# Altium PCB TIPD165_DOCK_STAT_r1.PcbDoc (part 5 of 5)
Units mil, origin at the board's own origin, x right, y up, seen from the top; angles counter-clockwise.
Board outline 6950 x 2800 mil, 2 copper layers (Primary Side, Secondary Side), stack 12.7 mil thick; 32 components, 163 nets, 1211 pads, 80 vias.
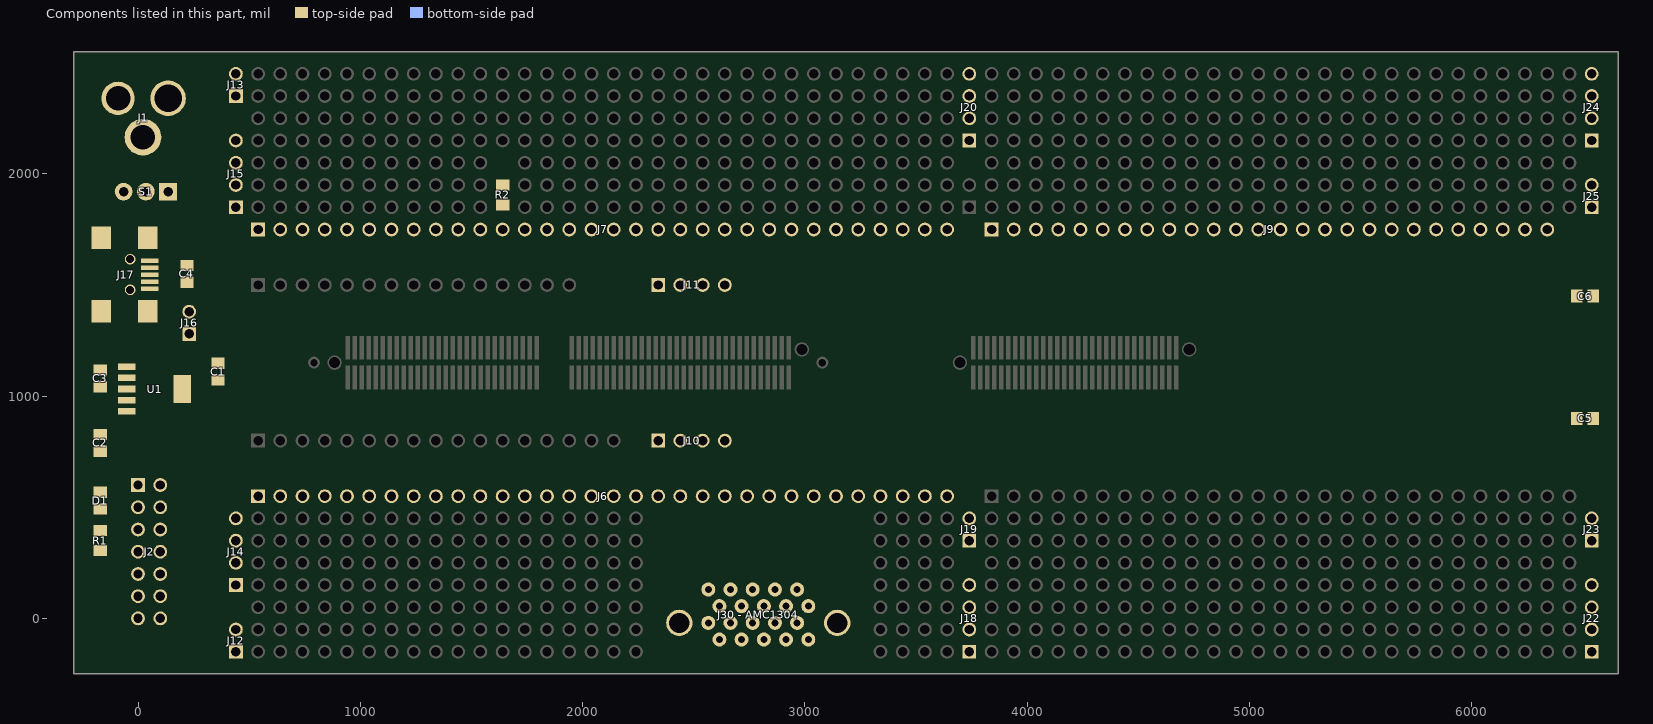
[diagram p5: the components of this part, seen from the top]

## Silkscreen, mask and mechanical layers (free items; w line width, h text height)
Primary Silkscreen:
  circle w8: c5627.38,1435 r12.38
  lines w8: 5604.5,1346.5 5609.75,1346.5 5624,1411.75 5619.5,1411.75 ; 5604.68,1346.37 5618.93,1411.62 ; 5491.25,1381 5493.5,1375.75 5497.25,1369.75 5510,1359.25 5516.75,1350.25 5525,1337.5 5535.5,1331.5 5543.75,1331.5 5547.5,1334.5 5555,1339.75 5558,1338.25 5562.5,1333.75 5568.5,1325.5 5576.75,1312.75 5576.75,1309 5580.5,1299.25 5584.25,1294 5591,1285.75 5603.75,1279.75 5613.5,1274.5 5621,1273.75 5623.25,1276 5624.75,1279.75 5623.25,1282.75 5621.75,1287.25 5621,1294 5624,1303.75 5627,1309.75 5634.5,1314.25 5640.5,1317.25 5648.75,1321 5656.25,1324 5665.25,1327 5675.75,1331.5 5684.75,1335.25 5687,1338.25 5689.25,1346.5 5689.25,1351.75 5687.75,1359.25 5687.75,1364.5 5684.75,1370.5 5681.75,1375.75 5678.75,1378 5677.25,1381 5677.25,1387.75 5676.5,1394.5 5675.75,1400.5 5674.25,1403.5 5675.75,1403.5 5674.25,1407.25 5671.25,1411 5668.25,1411.75 5663,1412.5 5660.75,1412.5 5660,1414 5651.75,1414 5648,1412.5 5645,1412.5 5639.75,1412.5 5638.25,1411.75 5634.5,1411 5629.25,1389.25 5649.5,1389.25 5646.5,1376.5 5627,1376.5 5620.25,1345.75 5621.75,1345 5623.25,1343.5 5624,1342 5624,1340.5 5624,1337.5 5621.75,1335.25 5621.75,1334.5 5615.75,1332.25 5612,1331.5 5607.5,1331.5 5601.5,1333.75 5596.25,1336.75 5593.25,1339.75 5593.25,1342 5601.5,1376.5 5580.5,1376.5 5585,1390 5603.75,1390 5609.75,1412.5 5606.75,1414 5600,1417 5598.5,1420 5594,1423.75 5594,1458.25 5543,1458.25 5543,1381 5491.25,1381
  lines w10: 899.69,998.13 598.28,998.13 598.28,1303.72 899.69,1303.72 ; 1828.08,998.13 1916.18,998.13 ; 1828.08,1303.72 1916.18,1303.72 ; 2970.56,998.13 3271.98,998.13 3271.98,1258.72 3226.98,1303.72 2970.56,1303.72 ; 3713.39,998.13 3635.4,998.13 3635.4,1303.72 3713.39,1303.72 ; 4712,998.13 4791.39,998.13 4791.39,1273.72 4761.39,1303.72 4713,1303.72 ; 490,750 490,850 2190,850 2190,750 490,750 ; 490,1450 490,1550 1990,1550 1990,1450 490,1450 ; 3690,1800 3790,1800 3790,2000 3690,2000 3690,1800 ; 3790,500 3790,600 6490,600 6490,500 3790,500
  text "GND" at 371.5,2355.69 h35 r90
  text "+5V in" at 293.33,2128.7 h35 r90
  text "GND" at 3755.75,2022.82 h27.5 r90
  text "GND" at 6555.75,2022.82 h27.5 r90
  text "3V3" at 371.5,1864.35 h35 r90
  text "EXT-ON" at -153.5,1845.37 h35 r90
  text "USB-ON" at 262.5,1836.21 h35 r90
  text "3V3" at 3755.75,1726.21 h27.5 r90
  text "3V3" at 6555.75,1725.71 h27.5 r90
  text "PIN" at 465,1700 h40 r90
  text "56" at 865,1632.63 h40 r90
  text "60" at 1065,1632.82 h40 r90
  text "62" at 1165,1632.82 h40 r90
  text "68" at 1365,1632.82 h40 r90
  text "76" at 1765,1632.63 h40 r90
  text "86" at 2165,1632.63 h40 r90
  text "96" at 2665,1632.63 h40 r90
  text "50" at 565,1630.73 h40 r90
  text "52" at 665,1630.73 h40 r90
  text "58" at 965,1630.73 h40 r90
  text "64" at 1265,1630.92 h40 r90
  text "70" at 1465,1630.73 h40 r90
  text "72" at 1565,1630.73 h40 r90
  text "78" at 1865,1630.73 h40 r90
  text "80" at 1965,1630.73 h40 r90
  text "82" at 2065,1630.73 h40 r90
  text "88" at 2265,1630.73 h40 r90
  text "90" at 2365,1630.73 h40 r90
  text "92" at 2465,1630.73 h40 r90
  text "54" at 765,1628.82 h40 r90
  text "74" at 1665,1628.82 h40 r90
  text "94" at 2565,1628.82 h40 r90
  text "116" at 3465,1609.59 h40 r90
  text "110" at 3265,1607.68 h40 r90
  text "118" at 3565,1607.68 h40 r90
  text "114" at 3365,1605.78 h40 r90
  text "166" at 5865,1605.4 h40 r90
  text "106" at 3065,1603.3 h40 r90
  text "126" at 4065,1603.3 h40 r90
  text "146" at 4965,1603.3 h40 r90
  text "156" at 5465,1603.3 h40 r90
  text "160" at 5565,1603.5 h40 r90
  text "162" at 5665,1603.5 h40 r90
  text "168" at 5965,1603.5 h40 r90
  text "176" at 6365,1603.3 h40 r90
  text "164" at 5765,1601.59 h40 r90
  text "100" at 2765,1601.4 h40 r90
  text "102" at 2865,1601.4 h40 r90
  text "108" at 3165,1601.4 h40 r90
  text "120" at 3665,1601.4 h40 r90
  text "122" at 3865,1601.4 h40 r90
  text "128" at 4165,1601.4 h40 r90
  text "130" at 4265,1601.4 h40 r90
  text "132" at 4365,1601.4 h40 r90
  text "138" at 4565,1601.4 h40 r90
  text "140" at 4665,1601.4 h40 r90
  text "142" at 4765,1601.4 h40 r90
  text "148" at 5065,1601.4 h40 r90
  text "150" at 5165,1601.4 h40 r90
  text "152" at 5265,1601.4 h40 r90
  text "170" at 6065,1601.4 h40 r90
  text "172" at 6165,1601.4 h40 r90
  text "104" at 2965,1599.5 h40 r90
  text "124" at 3965,1599.5 h40 r90
  text "134" at 4465,1599.5 h40 r90
  text "144" at 4865,1599.5 h40 r90
  text "154" at 5365,1599.5 h40 r90
  text "174" at 6265,1599.5 h40 r90
  text "ANA" at 465,1445 h40 r90
  text "16" at 765,1385.92 h40 r90
  text "12" at 565,1384.01 h40 r90
  text "18" at 865,1384.01 h40 r90
  text "14" at 665,1382.11 h40 r90
  text "26" at 1165,1379.63 h40 r90
  text "36" at 1665,1379.63 h40 r90
  text "20" at 965,1377.73 h40 r90
  text "28" at 1265,1377.73 h40 r90
  text "30" at 1365,1377.73 h40 r90
  text "32" at 1465,1377.73 h40 r90
  text "40" at 1765,1377.73 h40 r90
  text "42" at 1865,1377.73 h40 r90
  text "24" at 1065,1375.82 h40 r90
  text "44" at 1965,1375.82 h40 r90
  text "GND" at 2440,1375 h40
  text "34" at 1565,1370.82 h40 r90
  text "5V" at 352.5,1302.18 h35 r90
  text "POWER ONLY" at -180.77,1267.5 h35
  text "TEXAS INSTRUMENTS" at 5238.44,1156.51 h75
  text "TIPD165 Docking Station [Rev. 1]" at 5221.92,1015.48 h50
  text "GND" at 2440,875 h40
  text "11" at 665,870 h40 r90
  text "13" at 765,870 h40 r90
  text "15" at 865,870 h40 r90
  text "17" at 965,870 h40 r90
  text "09" at 565,865 h40 r90
  text "21" at 1065,865 h40 r90
  text "23" at 1165,865 h40 r90
  text "25" at 1265,865 h40 r90
  text "27" at 1365,865 h40 r90
  text "29" at 1465,865 h40 r90
  text "31" at 1565,865 h40 r90
  text "33" at 1665,865 h40 r90
  text "37" at 1765,865 h40 r90
  text "39" at 1865,865 h40 r90
  text "41" at 1965,865 h40 r90
  text "43" at 2065,865 h40 r90
  text "45" at 2165,865 h40 r90
  text "ANA" at 465,745 h40 r90
  text "49" at 565,615 h40 r90
  text "51" at 665,615 h40 r90
  text "53" at 765,615 h40 r90
  text "55" at 865,615 h40 r90
  text "57" at 965,615 h40 r90
  text "59" at 1065,615 h40 r90
  text "61" at 1165,615 h40 r90
  text "63" at 1265,615 h40 r90
  text "67" at 1365,615 h40 r90
  text "69" at 1465,615 h40 r90
  text "71" at 1565,615 h40 r90
  text "73" at 1665,615 h40 r90
  text "75" at 1765,615 h40 r90
  text "77" at 1865,615 h40 r90
  text "79" at 1965,615 h40 r90
  text "81" at 2065,615 h40 r90
  text "85" at 2165,615 h40 r90
  text "87" at 2265,615 h40 r90
  text "89" at 2365,615 h40 r90
  text "91" at 2465,615 h40 r90
  text "93" at 2565,615 h40 r90
  text "95" at 2665,615 h40 r90
  text "99" at 2765,615 h40 r90
  text "101" at 2865,615 h40 r90
  text "103" at 2965,615 h40 r90
  text "105" at 3065,615 h40 r90
  text "107" at 3165,615 h40 r90
  text "109" at 3265,615 h40 r90
  text "113" at 3365,615 h40 r90
  text "115" at 3465,615 h40 r90
  text "117" at 3565,615 h40 r90
  text "119" at 3665,615 h40 r90
  text "121" at 3865,615 h40 r90
  text "123" at 3965,615 h40 r90
  text "125" at 4065,615 h40 r90
  text "127" at 4165,615 h40 r90
  text "129" at 4265,615 h40 r90
  text "131" at 4365,615 h40 r90
  text "133" at 4465,615 h40 r90
  text "137" at 4565,615 h40 r90
  text "139" at 4665,615 h40 r90
  text "141" at 4765,615 h40 r90
  text "143" at 4865,615 h40 r90
  text "145" at 4965,615 h40 r90
  text "147" at 5065,615 h40 r90
  text "149" at 5165,615 h40 r90
  text "151" at 5265,615 h40 r90
  text "153" at 5365,615 h40 r90
  text "155" at 5465,615 h40 r90
  text "159" at 5565,615 h40 r90
  text "161" at 5665,615 h40 r90
  text "163" at 5765,615 h40 r90
  text "165" at 5865,615 h40 r90
  text "167" at 5965,615 h40 r90
  text "169" at 6065,615 h40 r90
  text "171" at 6165,615 h40 r90
  text "173" at 6265,615 h40 r90
  text "175" at 6365,615 h40 r90
  text "177" at 6465,615 h40 r90
  text "1" at -76,585 h25
  text "3V3" at 3755.75,525.71 h27.5 r90
  text "3V3" at 6555.75,525.71 h27.5 r90
  text "PIN" at 465,515 h40 r90
  text "GND" at 3755.75,222.82 h27.5 r90
  text "GND" at 6555.75,222.82 h27.5 r90
  text "3V3" at 371.5,150 h35 r90
  text "14" at 166,-16 h25
  text "JTAG" at -45,-150 h50
  text "GND" at 371.5,-150 h35 r90
  text "Primary Side Silkscreen" at 7579.95,-4801.77 h75
Drill Drawing:
  drawing of 181 lines, arcs and shapes, not listed
  text "Layer 1 - Primary Side" at -890,5272.73 h75
  text "Finished - 3 oz. Copper" at -3541,5265 h50
  text "Er = 4.3 - THICKNESS = FABRICATOR MAY DETERMINE" at -4274.62,4968.26 h62.5
  text "0.062\" +/- 0.007\"" at -6474.14,4956.65 h75
  text "Finished  - 3 oz. Copper" at -3561,4655 h50
  text "Layer 2 - Secondary Side" at -890,4647.73 h75
  text "FABRICATION NOTES:" at -6316,4090 h56.25
  text "1. NUMBER OF LAYERS = 2" at -6316,3865 h56.25
  text "2. UNLESS OTHERWISE SPECIFIED THE PRINTED WIRING BOARD" at -6334.75,3733.75 h56.25
  text "SHALL MEET THE REQUIREMENTS OF IPC-6012 CLASS 2." at -6184.75,3583.75 h56.25
  text "3. ACCEPTABILIITY TO IPC-A-600 CLASS 2." at -6336,3420 h56.25
  text "4. MATERIAL:" at -6334.75,3265 h56.25
  text "A. TYPE: FR4 OR EQUIVALENT" at -6091,3115 h56.25
  text "B. RAW Cu WEIGHT OUTER LAYERS:  2 Oz." at -6091,2965 h56.25
  text "C. RAW Cu WEIGHT INNER SIGNAL LAYERS:  N/A" at -6085,2825 h56.25
  text "D. RAW Cu WEIGHT INNER PLANE LAYERS:  N/A" at -6091,2665 h56.25
  text "E.     HI Tg      RoHS       HALOGEN FREE" at -6091,2515 h56.25
  text "2550mils" at -1420,2510 h75
  text "5. PROCESSING:" at -6316,2365 h56.25
  text "A. COPPER THEIVING ALLOWED ON OUTER LAYERS KEEPING A MINIMUM OF 0.200'" at -6091,2215 h56.25
  text "B. REMOVE ALL UNUSED PADS ON ARTWORK ON ALL INNER LAYERS." at -6091,2065 h56.25
  text "C. ETCH DATE CODE AND UL RECOGNIZED VENDOR MARK ON SECONDARY SIDE." at -6091,1915 h56.25
  text "6. IMPEDANCE:" at -6316,1765 h56.25
  text "A. USE REQUIRMENTS IN STACKUP. FABRICATOR HAS PERMISSION TO CHANGE THICKNESS" at -6091,1615 h56.25
  text "AND TRACE WIDTHS IN ORDER TO MEET IMPEDANCE REQUIRMENTS." at -5941,1465 h56.25
  text "55mil" at 1130,1340 h75 r90
  text "0" at 746.25,1319.32 h75 r90
  text "B. NON-CONTROLLED TRACES TO BE WITHIN 20% OF SPECIFIED APERTURE" at -6091,1315 h56.25
  text "0" at 1113.75,1264.04 h75 r90
  text "VALUE IN ARTWORK." at -5941,1165 h56.25
  text "-55mil" at 790,1120 h75 r90
  text "7. Cu PLATING:" at -6316,1015 h56.25
  text "A. UNLESS OTHERWISE SPECIFIED, HOLE DIMENSIONS ARE FOR FINISHED HOLES." at -6091,865 h56.25
  text "B. UNLESS OTHERWISE SPECIFIED, HOLE BARREL THICKNESS TO BE 0.001\" MIN." at -6091,715 h56.25
  text "8. FINISH PLATING:" at -6316,565 h56.25
  text "FINISH ALL EXPOSED PADS WITH:" at -5341,565 h56.25
  text "ELECTROLESS NICKEL/IMMERSION GOLD (ENIG)" at -5716,415 h56.25
  text "IMMERSION SILVER (ENIG)" at -5716,265 h56.25
  text "TIN/LEAD (HASL)" at -5716,115 h56.25
  text "HARD GOLD OVER NICKEL  30u/80u" at -5716,-35 h56.25
  text "0" at -940,-45 h75
  text "WHITE TIN" at -5716,-185 h56.25
  text "-250mils" at -1440,-295 h75
  text "ORGANIC SOLDERABILITY PRESERVATIVE (OSP)" at -5716,-335 h56.25
  text "LEAD FREE HASL" at -5716,-485 h56.25
  text "9. SOLDERMASK:" at -6316,-635 h56.25
  text "A. LPI GREEN SOLDER MASK OVER BARE COPPER BOTH SIDES." at -6091,-785 h56.25
  text "B. SOLDER MASK REGISTRATION TO BE WITHIN +/-.003\" OF RELEVANT LAYER." at -6091,-935 h56.25
  text "0" at 50,-940 h75 r90
  text "C. NO MASK TO APPEAR ON PADS" at -6091,-1085 h56.25
  text "6660mils" at 6700,-1210 h75 r90
  text "10. SILKSCREEN:" at -6316,-1235 h56.25
  text "A. USE WHITE NON-CONDUCTIVE INK." at -6091,-1385 h56.25
  text "-290mils" at -250,-1420 h75 r90
  text "B. NO SILKSCREEN TO APPEAR ON PADS." at -6091,-1535 h56.25
  text "11. WARP AND TWIST NOT TO EXCEED .010 INCH/INCH." at -6316,-1685 h56.25
  text "12. MILLING:" at -6316,-1835 h56.25
  text "A. ALL BOARD DIMENSIONS TO BE HELD TO WITHIN 0.005\"." at -6091,-1985 h56.25
  text "B. IF NO DIMENSIONS PRESENT, USE BOARD OUTLINE IN DD.PHO (THIS DRAWING)" at -6091,-2135 h56.25
  text "TO FEED DIRECTLY INTO MILLING PROCESSOR." at -5941,-2285 h56.25
  text "12. SPECIAL FEATURES:" at -6316,-2435 h56.25
  text "\"VIA IN PAD\"  PLUGGED [NON-CONDUCTIVE] VIAS PLATED OVER FLAT AND FLUSH" at -5716,-2585 h56.25
  text "\"VIA IN PAD\"  PLUGGED VIAS [CONDUCTIVE] PLATED OVER FLAT AND FLUSH" at -5716,-2735 h56.25
  text "BLIND VIAS" at -5716,-2885 h56.25
  text "BURIED VIAS" at -5716,-3035 h56.25
Primary Assembly Drawing:
  lines w1: -4928.1,-1085.94 -4685.47,-1085.94 ; -4928.1,1485.89 -4685.47,1485.89 ; -4928.1,3766.56 -4685.47,3766.56 ; -4831.83,1363.31 -4701.51,1486.01 -4831.83,1606.14 ; -2744.47,-3851.86 -2744.47,-3609.24 ; -2744.47,6581.01 -2744.47,6823.64 ; -803.47,-3851.86 -803.47,-3609.24 ; -803.47,6581.01 -803.47,6823.64 ; 490,-200 3690,-200 3690,500 490,500 490,400 ; 490,1800 3690,1800 ; 490,2400 490,2500 3690,2500 3690,1800 ; 1258.84,-3851.86 1258.84,-3609.24 ; 1258.84,6581.01 1258.84,6823.64 ; 1822.51,-3606.2 1822.51,-1663.26 ; 1823.78,-2784.18 3691.99,-2784.18 ; 1823.78,-2634.73 3691.99,-2634.73 ; 1823.78,-2485.27 3691.99,-2485.27 ; 1823.78,-2335.81 3691.99,-2335.81 ; 1823.78,-2186.36 3691.99,-2186.36 ; 1823.78,-2036.9 3691.99,-2036.9 ; 1823.78,-1850.08 3691.99,-1850.08 ; 1823.78,-1663.26 11314.31,-1663.26 ; 2757.89,-2784.18 2757.89,-1850.08 ; 3196.13,6725.42 3321.12,6580.83 3446.71,6725.42 ; 3321.15,-3851.86 3321.15,-3609.24 ; 3321.15,6581.01 3321.15,6823.64 ; 3691.99,-3606.2 3691.99,-1663.26 ; 3691.99,-2013.77 5597.57,-2013.77 ; 3790,-200 6540,-200 6540,500 3790,500 ; 3790,400 3790,500 ; 3790,2400 3790,2500 6540,2500 6540,1800 3790,1800 ; 5383.47,-3851.86 5383.47,-3609.24 ; 5383.47,6581.01 5383.47,6823.64 ; 5597.57,-3606.2 5597.57,-1663.26 ; 5597.57,-3456.74 7465.78,-3456.74 ; 5597.57,-3307.28 7465.78,-3307.28 ; 5597.57,-3157.83 7465.78,-3157.83 ; 5597.57,-3008.37 7465.78,-3008.37 11314.31,-3008.37 ; 5597.57,-2858.91 7465.78,-2858.91 ; 5597.57,-2709.45 7465.78,-2709.45 ; 5597.57,-2560 7465.78,-2560 ; 5597.57,-2410.54 7465.78,-2410.54 ; 5597.57,-2261.08 7465.78,-2261.08 ; 5597.57,-2111.63 7465.78,-2111.63 ; 5597.57,-1962.17 7465.78,-1962.17 ; 5597.57,-1812.71 7465.78,-1812.71 ; 6945.49,-3606.2 6945.49,-1663.26 ; 7445.78,-3851.86 7445.78,-3609.24 ; 7445.78,6581.01 7445.78,6823.64 ; 7465.78,-2148.99 11314.31,-2148.99 ; 7467.86,-3380.04 11305.86,-3380.04 ; 7468.58,-3606.2 7468.58,-1663.26 ; 7764.7,-3382.01 7764.7,-3008.37 ; 7931.03,5853.14 11327.78,5853.14 ; 7931.03,5998.71 11327.78,5998.71 ; 7931.03,6144.29 11327.78,6144.29 ; 7931.03,6289.86 11327.78,6289.86 ; 7931.03,6435.44 11327.78,6435.44 ; 7931.03,6581.01 7931.03,5707.56 11327.78,5707.56 ; 8125.13,5707.56 8125.13,6435.44 ; 8213.07,-3606.2 8213.07,-3382.01 ; 8319.23,5707.56 8319.23,6435.44 ; 8736.17,-3382.01 8736.17,-3008.37 ; 9386.78,-3851.86 9386.78,-3609.24 ; 9386.78,6581.01 9386.78,6823.64 ; 10006.55,-3606.2 10006.55,-3382.01 ; 10454.33,5707.56 10454.33,6435.44 ; 10842.53,5707.56 10842.53,6435.44 ; 10978.02,-3382.01 10978.02,-3008.37 ; 11327.78,-1085.94 11570.4,-1085.94 ; 11327.78,1485.89 11570.4,1485.89 ; 11327.78,3766.56 11570.4,3766.56 ; 11471.71,1364.59 11307.62,1484.72 11471.71,1605.28 ; 11473.35,1364.57 11473.35,1607.2 ; 3321.15,-3609.24 3199.84,-3754.81 3442.47,-3754.81 3321.15,-3609.24 ; 3690,1800 3790,1800 ; 3690,1800 3690,2000 3790,2000 3790,1800 ; 3790,500 3790,600 6490,600 6490,500 3790,500 ; -4928.1,-3851.86 11570.4,-3851.86 11570.4,6823.64 -4928.1,6823.64 -4928.1,-3851.86 ; -4700.65,-3609.24 11312.6,-3609.24 11312.6,6581.01 -4700.65,6581.01 -4700.65,-3609.24 ; 490,750 490,850 2190,850 2190,750 490,750 ; 490,1450 490,1550 1990,1550 1990,1450 490,1450 ; 613.28,1013.13 899.69,1013.13 899.69,1040.69 2970.56,1040.69 2970.56,1013.13 3256.98,1013.13 3256.98,1250.34 3218.59,1288.72 2970.56,1288.72 2970.56,1261.17 899.69,1261.17 899.69,1288.72 613.28,1288.72 613.28,1013.13 ; 3650.4,1014.39 3651.66,1013.13 3713.39,1013.13 3713.39,1040.69 4713.39,1040.69 4713.39,1013.13 4776.39,1013.13 4776.39,1266.36 4754.02,1288.72 4713.39,1288.72 4713.39,1261.17 3713.39,1261.17 3713.39,1288.72 3650.4,1288.72 3650.4,1014.39
  text "2" at 8294.97,6634.39 h103.98
  text "8" at -3836.28,6629.54 h103.98
  text "7" at -1773.97,6629.54 h103.98
  text "6" at 167.03,6629.54 h103.98
  text "5" at 2229.34,6629.54 h103.98
  text "4" at 4170.34,6629.54 h103.98
  text "3" at 6353.97,6629.54 h103.98
  text "1" at 10357.28,6629.54 h103.98
  text "REVISIONS" at 9338.25,6483.96 h43.33
  text "REV." at 7984.39,6338.38 h27.73
  text "REV." at 8149.39,6338.39 h27.73
  text "DESCRIPTION" at 9119.89,6338.39 h27.73
  text "DATE" at 10551.38,6338.39 h27.73
  text "APPROVED" at 10915.32,6338.39 h27.73
  text "Notes:" at -4358.01,6146.01 h150
  text "1) Refer to BOM for stuffing options." at -4223.01,5898.51 h93.75
  text "2) Observe polarity on diodes and capacitors." at -4260.51,5666.01 h93.75
  text "D" at -4855.31,5028.21 h103.98
  text "D" at 11400.57,5028.21 h103.98
  text "C" at -4855.31,2601.96 h103.98
  text "C" at 11400.57,2601.96 h103.98
  text "J27" at 590,2415 h50
  text "J29" at 3890,2415 h50
  text "HEADERS: J4, J5, J10, AND J11 TALLER THAN OTHER HEADERS" at 880,1870 h50
  text "J21" at 3770,1860 h50 r90
  text "J5" at 590,1465 h50
  text "J4" at 590,765 h50
  text "J26" at 590,415 h50
  text "J28" at 3890,415 h50
  text "HEADERS: J4, J5, J10, AND J11 TALLER THAN OTHER HEADERS" at 875,380 h50
  text "B" at -4855.31,175.71 h103.98
  text "B" at 11400.57,175.71 h103.98
  text "J2: REMOVE PIN 6" at 280,-130 h50 r90
  text "Primary Side" at 2655.07,-935.61 h133.44
  text "DWN:" at 5638.77,-1763.98 h42.7
  text "APPLICATION" at 2458.85,-1770.01 h42.7
  text "CONTRACT NO." at 3766.6,-1770.01 h42.7
  text "SBL          7/12" at 6395.4,-1770.61 h53.38
  text "CHK:" at 5638.77,-1913.44 h42.7
  text "TEXAS INSTRUMENTS" at 8365.81,-1950.19 h133.44
  text "USED ON" at 2070.48,-1969.48 h42.7
  text "NEXT ASSY." at 2929.86,-1969.48 h42.7
  text "P.E.:" at 5638.77,-2062.89 h42.7
  text "UNLESS OTHERWISE SPECIFIED" at 3770.56,-2137.62 h53.38
  text "DES.ENG.:" at 5638.77,-2212.35 h42.7
  text "TITLE:" at 7540.51,-2261.08 h42.7
  text "1. TOLERANCES:" at 3770.56,-2343.13 h42.7
  text "P.C.:" at 5638.77,-2361.81 h42.7
  text "ASSEMBLY DRAWING," at 8611.68,-2378.27 h106.75
  text "A" at -4855.31,-2396.11 h103.98
  text "A" at 11400.57,-2396.11 h103.98
  text "+" at 4443.11,-2417.86 h21.35
  text "0.26 (.010)" at 4555.2,-2455.22 h42.7
  text "-" at 4443.11,-2466.25 h21.35
  text "LINEAR =" at 3901.33,-2473.9 h42.7
  text "Q.C.:" at 5638.77,-2511.27 h42.7
  text "0" at 4798.07,-2529.95 h21.35
  text "+" at 4499.16,-2548.63 h21.35
  text "ANGULAR =" at 3901.33,-2585.99 h42.7
  text "0.50" at 4611.25,-2585.99 h42.7
  text "-" at 4499.16,-2597.03 h21.35
  text "C.M.:" at 5638.77,-2679.4 h42.7
  text "DockingStn_HSEC8" at 8817.41,-2707.51 h80.07
  text "2. ALL DIMENSIONS ARE IN" at 3770.56,-2810.18 h42.7
  text "REL:" at 5638.77,-2810.18 h42.7
  text "MATERIAL:  SEE NOTE" at 1902.34,-2922.27 h42.7
  text "MM (INCHES)." at 3901.33,-2922.27 h42.7
  text "MFG:" at 5638.77,-2959.64 h42.7
  text "FINISH:  SEE NOTE" at 1902.34,-3053.05 h42.7
  text "SIZE" at 7503.15,-3101.78 h42.7
  text "CAGE CODE NO." at 7858.11,-3101.78 h42.7
  text "DRAWING NO." at 8810.9,-3101.78 h42.7
  text "REV:" at 11034.08,-3101.78 h42.7
  text "ENG.MGR:" at 5638.77,-3109.09 h42.7
  text "3. INTERPRET DRAWING IN" at 3770.56,-3202.5 h42.7
  text "?" at 10081.82,-3240.98 h90
  text "OTHER:" at 5638.77,-3258.55 h42.7
  text "4.1" at 11100,-3270 h90
  text "C" at 7574.97,-3309.37 h106.75
  text "ACCORDANCE WITH" at 3901.33,-3314.6 h42.7
  text "OTHER:" at 5638.77,-3408.01 h42.7
  text "DOD-STD-100." at 3901.33,-3426.69 h42.7
  text "SCALE:" at 7520.84,-3521.03 h42.7
  text "SHEET     OF" at 10068.89,-3521.03 h42.7
  text "DO NOT SCALE DRAWING" at 2103.15,-3523.12 h42.7
  text "1:1" at 7933.9,-3525.94 h53.38
  text "1    2" at 10407.9,-3533.11 h53.38
  text "OTHER:" at 5638.77,-3557.46 h42.7
  text "2" at 8294.97,-3798.49 h103.98
  text "8" at -3836.28,-3803.34 h103.98
  text "7" at -1773.97,-3803.34 h103.98
  text "6" at 167.03,-3803.34 h103.98
  text "5" at 2229.34,-3803.34 h103.98
  text "4" at 4170.34,-3803.34 h103.98
  text "3" at 6353.97,-3803.34 h103.98
  text "1" at 10357.28,-3803.34 h103.98
Secondary Assembly Drawing:
  lines w1: -4937.38,-1063.93 -4694.76,-1063.93 ; -4937.38,1507.9 -4694.76,1507.9 ; -4937.38,3788.57 -4694.76,3788.57 ; -4840.33,1386.59 -4840.33,1629.21 ; -4838.69,1386.61 -4674.6,1506.74 -4838.69,1627.3 ; -4694.76,5729.57 -1298.01,5729.57 -1298.01,6603.02 ; -4694.76,5875.15 -1298.01,5875.15 ; -4694.76,6020.72 -1298.01,6020.72 ; -4694.76,6166.3 -1298.01,6166.3 ; -4694.76,6311.87 -1298.01,6311.87 ; -4694.76,6457.45 -1298.01,6457.45 ; -4681.29,-2986.36 -832.76,-2986.36 1035.45,-2986.36 ; -4681.29,-2126.98 -832.76,-2126.98 ; -4681.29,-1641.24 4809.24,-1641.24 ; -4672.84,-3358.02 -834.84,-3358.02 ; -4345,-3360 -4345,-2986.36 ; -4209.51,5729.57 -4209.51,6457.45 ; -3821.31,5729.57 -3821.31,6457.45 ; -3373.53,-3584.19 -3373.53,-3360 ; -2753.76,-3829.85 -2753.76,-3587.23 ; -2753.76,6603.02 -2753.76,6845.65 ; -2103.15,-3360 -2103.15,-2986.36 ; -1686.21,5729.57 -1686.21,6457.45 ; -1580.05,-3584.19 -1580.05,-3360 ; -1492.11,5729.57 -1492.11,6457.45 ; -1131.67,-3360 -1131.67,-2986.36 ; -835.56,-3584.19 -835.56,-1641.24 ; -832.76,-3434.73 1035.45,-3434.73 ; -832.76,-3285.27 1035.45,-3285.27 ; -832.76,-3135.81 1035.45,-3135.81 ; -832.76,-2836.9 1035.45,-2836.9 ; -832.76,-2687.44 1035.45,-2687.44 ; -832.76,-2537.99 1035.45,-2537.99 ; -832.76,-2388.53 1035.45,-2388.53 ; -832.76,-2239.07 1035.45,-2239.07 ; -832.76,-2089.62 1035.45,-2089.62 ; -832.76,-1940.16 1035.45,-1940.16 ; -832.76,-1790.7 1035.45,-1790.7 ; -812.76,-3829.85 -812.76,-3587.23 ; -812.76,6603.02 -812.76,6845.65 ; -312.46,-3584.19 -312.46,-1641.24 ; 1035.45,-3584.19 1035.45,-1641.24 ; 1035.45,-1991.76 2941.03,-1991.76 ; 1249.55,-3829.85 1249.55,-3587.23 ; 1249.55,6603.02 1249.55,6845.65 ; 2941.03,-3584.19 2941.03,-1641.24 ; 2941.03,-2762.17 4809.24,-2762.17 ; 2941.03,-2612.71 4809.24,-2612.71 ; 2941.03,-2463.26 4809.24,-2463.26 ; 2941.03,-2313.8 4809.24,-2313.8 ; 2941.03,-2164.34 4809.24,-2164.34 ; 2941.03,-2014.89 4809.24,-2014.89 ; 2941.03,-1828.07 4809.24,-1828.07 ; 3186.31,6747.43 3311.9,6602.85 3436.89,6747.43 ; 3311.87,-3829.85 3311.87,-3587.23 ; 3311.87,6603.02 3311.87,6845.65 ; 3875.13,-2762.17 3875.13,-1828.07 ; 4810.51,-3584.19 4810.51,-1641.24 ; 5374.18,-3829.85 5374.18,-3587.23 ; 5374.18,6603.02 5374.18,6845.65 ; 7436.49,-3829.85 7436.49,-3587.23 ; 7436.49,6603.02 7436.49,6845.65 ; 9377.49,-3829.85 9377.49,-3587.23 ; 9377.49,6603.02 9377.49,6845.65 ; 11318.49,-1063.93 11561.12,-1063.93 ; 11318.49,1507.9 11561.12,1507.9 ; 11318.49,3788.57 11561.12,3788.57 ; 11464.86,1385.32 11334.53,1508.02 11464.86,1628.15 ; 3311.87,-3587.23 3433.18,-3732.8 3190.55,-3732.8 3311.87,-3587.23 ; -4937.38,-3829.85 11561.12,-3829.85 11561.12,6845.65 -4937.38,6845.65 -4937.38,-3829.85 ; -4679.57,-3587.23 11333.68,-3587.23 11333.68,6603.02 -4679.57,6603.02 -4679.57,-3587.23
  text "2" at -1661.95,6656.4 h103.98
  text "1" at -3724.26,6651.55 h103.98
  text "3" at 279.05,6651.55 h103.98
  text "4" at 2462.68,6651.55 h103.98
  text "5" at 4403.68,6651.55 h103.98
  text "6" at 6465.99,6651.55 h103.98
  text "7" at 8406.99,6651.55 h103.98
  text "8" at 10469.3,6651.55 h103.98
  text "REVISIONS" at -2705.23,6505.97 h43.33
  text "APPROVED" at -4282.3,6360.4 h27.73
  text "DATE" at -3918.36,6360.4 h27.73
  text "DESCRIPTION" at -2486.87,6360.4 h27.73
  text "REV." at -1516.37,6360.4 h27.73
  text "REV." at -1351.37,6360.39 h27.73
  text "Notes:" at 10991.03,6168.02 h150
  text "1) Refer to BOM for stuffing options." at 10856.03,5920.52 h93.75
  text "2) Observe polarity on diodes and capacitors." at 10893.53,5688.02 h93.75
  text "D" at -4767.55,5050.22 h103.98
  text "D" at 11488.33,5050.22 h103.98
  text "C" at -4767.55,2623.97 h103.98
  text "C" at 11488.33,2623.97 h103.98
  text "B" at -4767.55,197.72 h103.98
  text "B" at 11488.33,197.72 h103.98
  text "Secondary Side" at 3918.88,-927.49 h133.44
  text "DWN:" at 994.25,-1741.97 h42.7
  text "CONTRACT NO." at 2866.42,-1748 h42.7
  text "APPLICATION" at 4174.17,-1748 h42.7
  text "WSTS        2/11" at 237.62,-1748.6 h53.38
  text "CHK:" at 994.25,-1891.42 h42.7
  text "TEXAS INSTRUMENTS" at -1732.79,-1928.18 h133.44
  text "NEXT ASSY." at 3703.16,-1947.47 h42.7
  text "USED ON" at 4562.54,-1947.47 h42.7
  text "P.E.:" at 994.25,-2040.88 h42.7
  text "UNLESS OTHERWISE SPECIFIED" at 2862.47,-2115.61 h53.38
  text "DES.ENG.:" at 994.25,-2190.34 h42.7
  text "TITLE:" at -907.49,-2239.07 h42.7
  text "1. TOLERANCES:" at 2862.47,-2321.11 h42.7
  text "P.C.:" at 994.25,-2339.8 h42.7
  text "ASSEMBLY DRAWING," at -1978.65,-2356.26 h106.75
  text "A" at -4767.55,-2374.1 h103.98
  text "A" at 11488.33,-2374.1 h103.98
  text "+" at 2189.91,-2395.84 h21.35
  text "0.26 (.010)" at 2077.82,-2433.21 h42.7
  text "-" at 2189.91,-2444.24 h21.35
  text "LINEAR =" at 2731.69,-2451.89 h42.7
  text "Q.C.:" at 994.25,-2489.25 h42.7
  text "0" at 1834.95,-2507.94 h21.35
  text "+" at 2133.86,-2526.62 h21.35
  text "0.50" at 2021.77,-2563.98 h42.7
  text "ANGULAR =" at 2731.69,-2563.98 h42.7
  text "-" at 2133.86,-2575.01 h21.35
  text "C.M.:" at 994.25,-2657.39 h42.7
  text "C2000 600W HVPSFB EVM BOARD" at -1731.52,-2670.25 h80.07
  text "REL:" at 994.25,-2788.17 h42.7
  text "2. ALL DIMENSIONS ARE IN" at 2862.47,-2788.17 h42.7
  text "MM (INCHES)." at 2731.69,-2900.26 h42.7
  text "MATERIAL:  SEE NOTE" at 4730.68,-2900.26 h42.7
  text "MFG:" at 994.25,-2937.62 h42.7
  text "FINISH:  SEE NOTE" at 4730.68,-3031.03 h42.7
  text "REV:" at -4401.05,-3079.77 h42.7
  text "DRAWING NO." at -2177.88,-3079.77 h42.7
  text "CAGE CODE NO." at -1225.09,-3079.77 h42.7
  text "SIZE" at -870.12,-3079.77 h42.7
  text "ENG.MGR:" at 994.25,-3087.08 h42.7
  text "3. INTERPRET DRAWING IN" at 2862.47,-3180.49 h42.7
  text "OTHER:" at 994.25,-3236.54 h42.7
  text "C" at -941.95,-3287.36 h106.75
  text "ACCORDANCE WITH" at 2731.69,-3292.58 h42.7
  text "OTHER:" at 994.25,-3385.99 h42.7
  text "DOD-STD-100." at 2731.69,-3404.68 h42.7
  text "SHEET     OF" at -3435.87,-3499.02 h42.7
  text "SCALE:" at -887.82,-3499.02 h42.7
  text "DO NOT SCALE DRAWING" at 4529.88,-3501.1 h42.7
  text "1:1" at -1300.88,-3503.93 h53.38
  text "2    2" at -3774.88,-3511.1 h53.38
  text "OTHER:" at 994.25,-3535.45 h42.7
  text "2" at -1661.95,-3776.47 h103.98
  text "1" at -3724.26,-3781.33 h103.98
  text "3" at 279.05,-3781.33 h103.98
  text "4" at 2462.68,-3781.33 h103.98
  text "5" at 4403.68,-3781.33 h103.98
  text "6" at 6465.99,-3781.33 h103.98
  text "7" at 8406.99,-3781.33 h103.98
  text "8" at 10469.3,-3781.33 h103.98
Drill Drawing Format:
  lines w1: -7100.35,-2060 -6850.35,-2060 ; -7100.35,590 -6850.35,590 ; -7100.35,2940 -6850.35,2940 ; -7001.17,463.69 -6866.88,590.13 -7001.17,713.91 ; -4850.35,-4910 -4850.35,-4660 ; -4850.35,5840 -4850.35,6090 ; -2850.35,-4910 -2850.35,-4660 ; -2850.35,5840 -2850.35,6090 ; -725.35,-4910 -725.35,-4660 ; -725.35,5840 -725.35,6090 ; 1270.82,5988.8 1399.62,5839.82 1529.02,5988.8 ; 1399.65,-4910 1399.65,-4660 ; 1399.65,5840 1399.65,6090 ; 3282.6,-4657.56 3282.6,-3357.56 ; 3283.45,-4107.56 4533.45,-4107.56 ; 3283.45,-4007.56 4533.45,-4007.56 ; 3283.45,-3907.56 4533.45,-3907.56 ; 3283.45,-3807.56 4533.45,-3807.56 ; 3283.45,-3707.56 4533.45,-3707.56 ; 3283.45,-3607.56 4533.45,-3607.56 ; 3283.45,-3482.56 4533.45,-3482.56 ; 3283.45,-3357.56 9633.45,-3357.56 ; 3524.65,-4910 3524.65,-4660 ; 3524.65,5840 3524.65,6090 ; 3908.45,-4107.56 3908.45,-3482.56 ; 4533.45,-4657.56 4533.45,-3357.56 ; 4533.45,-3592.08 5808.45,-3592.08 ; 5649.65,-4910 5649.65,-4660 ; 5649.65,5840 5649.65,6090 ; 5808.45,-4657.56 5808.45,-3357.56 ; 5808.45,-4557.56 7058.45,-4557.56 ; 5808.45,-4457.56 7058.45,-4457.56 ; 5808.45,-4357.56 7058.45,-4357.56 ; 5808.45,-4257.56 7058.45,-4257.56 9633.45,-4257.56 ; 5808.45,-4157.56 7058.45,-4157.56 ; 5808.45,-4057.56 7058.45,-4057.56 ; 5808.45,-3957.56 7058.45,-3957.56 ; 5808.45,-3857.56 7058.45,-3857.56 ; 5808.45,-3757.56 7058.45,-3757.56 ; 5808.45,-3657.56 7058.45,-3657.56 ; 5808.45,-3557.56 7058.45,-3557.56 ; 5808.45,-3457.56 7058.45,-3457.56 ; 6149.65,5090 9649.65,5090 ; 6149.65,5240 9649.65,5240 ; 6149.65,5390 9649.65,5390 ; 6149.65,5540 9649.65,5540 ; 6149.65,5690 9649.65,5690 ; 6149.65,5840 6149.65,4940 9649.65,4940 ; 6349.65,4940 6349.65,5690 ; 6549.65,4940 6549.65,5690 ; 6710.32,-4657.56 6710.32,-3357.56 ; 7058.45,-3682.56 9633.45,-3682.56 ; 7059.84,-4506.24 9627.8,-4506.24 ; 7060.32,-4657.56 7060.32,-3357.56 ; 7258.45,-4507.56 7258.45,-4257.56 ; 7558.45,-4657.56 7558.45,-4507.56 ; 7649.65,-4910 7649.65,-4660 ; 7649.65,5840 7649.65,6090 ; 7908.45,-4507.56 7908.45,-4257.56 ; 8749.65,4940 8749.65,5690 ; 8758.45,-4657.56 8758.45,-4507.56 ; 9149.65,4940 9149.65,5690 ; 9408.45,-4507.56 9408.45,-4257.56 ; 9649.65,590 9899.65,590 ; 9649.65,2940 9899.65,2940 ; 9797.96,465.02 9628.88,588.8 9797.96,713.03 ; 9799.65,465 9799.65,715 ; 1399.65,-4660 1274.65,-4810 1524.65,-4810 1399.65,-4660 ; -7100.35,-4910 9899.65,-4910 9899.65,6090 -7100.35,6090 -7100.35,-4910 ; -6866,-4660 9634,-4660 9634,5840 -6866,5840 -6866,-4660
  text "2" at 6524.65,5895 h107.14
  text "8" at -5975.35,5890 h107.14
  text "7" at -3850.35,5890 h107.14
  text "6" at -1850.35,5890 h107.14
  text "5" at 274.65,5890 h107.14
  text "4" at 2274.65,5890 h107.14
  text "3" at 4524.65,5890 h107.14
  text "1" at 8649.65,5890 h107.14
  text "REVISIONS" at 7599.65,5740 h44.64
  text "REV." at 6204.65,5590 h28.57
  text "REV." at 6374.65,5590 h28.57
  text "DESCRIPTION" at 7374.65,5590 h28.57
  text "DATE" at 8849.65,5590 h28.57
  text "APPROVED" at 9224.65,5590 h28.57
  text "D" at -7025.35,4240 h107.14
  text "D" at 9724.65,4240 h107.14
  text "C" at -7025.35,1740 h107.14
  text "C" at 9724.65,1740 h107.14
  text "B" at -7025.35,-760 h107.14
  text "B" at 9724.65,-760 h107.14
  text "A" at -7025.35,-3410 h107.14
  text "A" at 9724.65,-3410 h107.14
  text "DWN:" at 5836.01,-3424.95 h28.57
  text "APPLICATION" at 3708.37,-3428.99 h28.57
  text "CONTRACT NO." at 4583.37,-3428.99 h28.57
  text "SBL               5/12" at 6161.01,-3438.01 h35.72
  text "CHK:" at 5836.01,-3524.95 h28.57
  text "TEXAS INSTRUMENTS" at 7630.44,-3561.02 h89.28
  text "USED ON" at 3448.51,-3562.45 h28.57
  text "NEXT ASSY." at 4023.51,-3562.45 h28.57
  text "P.E.:" at 5836.01,-3624.95 h28.57
  text "UNLESS OTHERWISE SPECIFIED" at 4586.01,-3674.95 h35.71
  text "DES.ENG.:" at 5836.01,-3724.95 h28.57
  text "TITLE:" at 7108.45,-3757.56 h28.57
  text "1. TOLERANCES:" at 4586.01,-3812.45 h28.57
  text "P.C.:" at 5836.01,-3824.95 h28.57
  text "+" at 5036.01,-3862.45 h14.29
  text "0.26 (.010)" at 5111.01,-3887.45 h28.57
  text "-" at 5036.01,-3894.83 h14.29
  text "LINEAR =" at 4673.51,-3899.95 h28.57
  text "Q.C.:" at 5836.01,-3924.95 h28.57
  text "FABRICATION DRAWING," at 7778.35,-3928.01 h71.43
  text "0" at 5273.51,-3937.45 h14.29
  text "+" at 5073.51,-3949.95 h14.29
  text "ANGULAR =" at 4673.51,-3974.95 h28.57
  text "0.50" at 5148.51,-3974.95 h28.57
  text "-" at 5073.51,-3982.33 h14.29
  text "C.M.:" at 5836.01,-4037.45 h28.57
  text "DockingStn_HSEC8_BL3" at 7857.45,-4072.48 h53.57
  text "2. ALL DIMENSIONS ARE IN" at 4586.01,-4124.95 h28.57
  text "REL:" at 5836.01,-4124.95 h28.57
  text "MATERIAL:  SEE NOTE" at 3336.01,-4199.95 h28.57
  text "MM (INCHES)." at 4673.51,-4199.95 h28.57
  text "MFG:" at 5836.01,-4224.95 h28.57
  text "FINISH:  SEE NOTE" at 3336.01,-4287.45 h28.57
  text "SIZE" at 7083.45,-4320.06 h28.57
  text "CAGE CODE NO." at 7320.95,-4320.06 h28.57
  text "DRAWING NO." at 7958.45,-4320.06 h28.57
  text "REV:" at 9445.95,-4320.06 h28.57
  text "ENG.MGR:" at 5836.01,-4324.95 h28.57
  text "3. INTERPRET DRAWING IN" at 4586.01,-4387.45 h28.57
  text "?" at 8776.57,-4420.44 h62.5
  text "OTHER:" at 5836.01,-4424.95 h28.57
  text "4.1" at 9501.69,-4432.18 h40
  text "B" at 7131.5,-4458.96 h71.43
  text "ACCORDANCE WITH" at 4673.51,-4462.45 h28.57
  text "OTHER:" at 5836.01,-4524.95 h28.57
  text "DOD-STD-100." at 4673.51,-4537.45 h28.57
  text "SCALE:" at 7095.29,-4600.58 h28.57
  text "SHEET     OF" at 8800.16,-4600.58 h28.57
  text "DO NOT SCALE DRAWING" at 3470.37,-4601.97 h28.57
  text "1:1" at 7371.66,-4603.86 h35.71
  text "1    1" at 9034,-4610 h35.71
  text "OTHER:" at 5836.01,-4624.95 h28.57
  text "2" at 6524.65,-4855 h107.14
  text "8" at -5975.35,-4860 h107.14
  text "7" at -3850.35,-4860 h107.14
  text "6" at -1850.35,-4860 h107.14
  text "5" at 274.65,-4860 h107.14
  text "4" at 2274.65,-4860 h107.14
  text "3" at 4524.65,-4860 h107.14
  text "1" at 8649.65,-4860 h107.14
